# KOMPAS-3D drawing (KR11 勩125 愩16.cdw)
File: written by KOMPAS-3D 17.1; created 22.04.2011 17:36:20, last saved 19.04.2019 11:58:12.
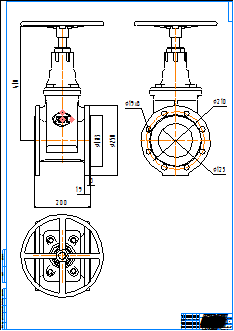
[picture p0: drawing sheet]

Title block, sheet 1: name: KR11 Ду125 Ру16; material: Внимание! Данный продукт является объектом авторского права ООО «Торговый Дом АДЛ». / Запрещается изменение, копирование, распространение / (в том числе путем копирования на другие сайты и ресурсы в Интернете) / или любое иное использование информации и объектов без предварительного / согласия правообладателя (ООО «Торговый Дом АДЛ»).; scale: 1:1; sheets: 1; organisation: ООО "Торговый дом АДЛ"; sheet format: A0; stored path: \\adlc.lan\data\АДЛ_ПКД\3D-модели\ADL production\Клиновые задвижки серии KR ГРАНАР\Клиновые задвижки KR11\KOMPAS 2D\KR11 Ду125 Ру16.cdw

Views: Спереди 4, Проекционный вид 5
Dimensions and other numbers on the sheet: 250; 183; 410; 3; 19; 200; 1:1; 1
